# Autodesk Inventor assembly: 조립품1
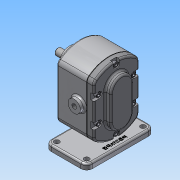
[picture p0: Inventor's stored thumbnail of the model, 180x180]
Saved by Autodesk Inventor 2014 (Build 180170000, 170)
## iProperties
Created: 2019-03
Part Number: 조립품1
Document SubType Name: Assembly
Designer: net
Author: net
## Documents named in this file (11)
- C:\Users\net\Desktop\490307V1045\OldVersions\조립품1.iam
- C:\Users\net\Desktop\490307V1045\본체.ipt
- C:\Users\net\Desktop\490307V1045\메인축.ipt
- C:\Users\net\Desktop\490307V1045\키 6 x 6 x 18.ipt
- C:\Users\net\Desktop\490307V1045\베어링부시.ipt
- C:\Users\net\Desktop\490307V1045\서브축.ipt
- C:\Users\net\Desktop\490307V1045\오일 실 16 28 7.ipt
- C:\Users\net\Desktop\490307V1045\스퍼기어.ipt
- C:\Users\net\Desktop\490307V1045\개스킷.ipt
- C:\Users\net\Desktop\490307V1045\커버.ipt
- C:\Users\net\Desktop\490307V1045\볼트 M5.ipt
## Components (1 placed, 1 different names)
1. 개스킷:1
